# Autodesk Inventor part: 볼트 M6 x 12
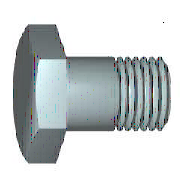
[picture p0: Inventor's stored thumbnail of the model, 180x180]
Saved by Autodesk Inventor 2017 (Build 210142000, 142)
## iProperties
IsCustomPart: 0
Created: 2012-02
Part Number: 볼트 M6 x 12
Material: 스테인리스강
Description: 6각 머리 나사. 제품 등급 C
Document SubType Name: Modeling
Standard: ISO 4018
Designer: mduedu
Standard Revision: Third edition 1999-08-15
Standards Organization: ISO
Language: ko-KR
Size Designation: M6 x 12
Categories: <MemberInstance><Categories><Category DisplayName="조임쇠" InternalName="e4da775c-781d-43d5-af7c-5136215cf5a6" Mnemonic="FSTN"><Category DisplayName="볼트" InternalN
Density: 8.08 g/cm^3
Appearance: 반광택
Author: mduedu
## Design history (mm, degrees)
node "WorkPlane1"
node "WorkPoint1"
node "MSC_A1"
node "MSC_PF1"
node "MSC_PT1"
body "Solid1"
node "스케치1"
sketch "스케치2"
  geometry: L1 (-5, 2.887)-(-5, -2.887); L2 (0, 5.773)-(-5, 2.887); L3 (5, 2.887)-(0, 5.773); L4 (5, -2.887)-(5, 2.887); L5 (0, -5.773)-(5, -2.887); L6 (-5, -2.887)-(0, -5.773); C1 r 5 at (0, 0); 1 further point
  constraints: 12 end point, 6 tangent, 2 parallel, 2 vertical, 1 centre point
  dimensions: "d1" = 10 diameter of C1 (= ParS); "d29" = 0 distance of point (0, 0) C1.centre; "d30" = 0 distance of C1.centre point (0, 0)
extrude "돌출1" new body sketch "스케치2" distance "d6" = 4 (= ParK); taper "d7" = 0 deg
revolve "회전1" stored, may be unused: angle "d14" = 360 deg
revolve "회전2" stored, may be unused: angle "d21" = 360 deg
chamfer "모따기1" distance "d22" = 0.5 (= 0.5 x PTC); stored, may be unused: second distance "d23" = 0.5 (= 0.5 x PTC), angle "d39" = 45 deg
fillet "모깎기1" dims "d24" = 0.25 (= r)
feature "스레드1" dims "d32" = 0, "b" = 10 (= NLG - 2 x PTC)
sketch "스케치3"
  geometry: L1 (5, 4)-(5.873, 4); L2 (5.873, 3.496)-(5, 4); L3 (5.873, 4)-(5.873, 3.496); L4 (0, -0.8)-(0, 4.8) reference; L5 (5.773, 0)-(5.773, 4) reference
  constraints: 6 end point, 1 horizontal, 1 vertical
  dimensions: "d25" = 0.1 distance between parallel lines of L5 L3; "d26" = 0 distance from line of L5.end L1; "d27" = 60 deg angle of L3 L2; "d28" = 5 distance from line of L4 L1.start (= 0.5 x ParS)
sketch "스케치4"
  geometry: L1 (0, -12)-(0, 0); L2 (-3, -12)-(0, -12); L3 (-3, 0)-(-3, -12); L4 (0, 0)-(-3, 0); L5 (0, -12)-(0, 0); L6 (-3.6, 0)-(0.6, 0) reference; L7 (0, -14.4)-(0, 2.4) reference
  constraints: 10 end point, 2 horizontal, 2 vertical
  dimensions: "d18" = 3 distance of L1.start L2.start (= 0.5 x NND); "d20" = 12 distance of L3.start L2.start (= NLG); "d33" = 0 distance between parallel lines of L7 L1; "d34" = 0 distance between parallel lines of L6 L4
other parameters: "NND" = 6 [user parameter; used in 2 equation terms], "NLG" = 12 [user parameter; used in 2 equation terms], "PTC" = 1 [user parameter; used in 3 equation terms], "ParK" = 4 [user parameter; used in 1 equation term], "ParS" = 10 [user parameter; used in 3 equation terms], "msp_es" = 5.77367 (= 0.577367 x ParS) [user parameter], "r" = 0.25 [user parameter; used in 1 equation term], "d2" = 15 (derived), "d4" = 17.32102 (derived), "d8" = 15 (derived), "d10" = 0 (derived), "d12" = 30 deg (derived), "d15" = 0 (derived), "d37" = 0, "d38" = 0, "d40" = 0, "d41" = 0, "d42" = 0, "THREADDIA" = 6 (= NND) [user parameter]
